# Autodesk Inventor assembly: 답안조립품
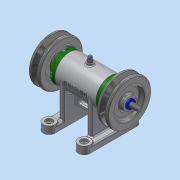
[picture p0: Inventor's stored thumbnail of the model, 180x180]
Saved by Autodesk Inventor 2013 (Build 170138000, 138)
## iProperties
Created: 2015-11
Part Number: 답안조립품
Document SubType Name: Assembly
Designer: ST1
Author: ST1
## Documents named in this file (11)
- C:\Users\ST1\Desktop\451109V1027\답안조립품.iam
- C:\Users\ST1\Desktop\451109V1027\1-본체.ipt
- C:\Users\ST1\Desktop\451109V1027\커버.ipt
- C:\Users\ST1\Desktop\451109V1027\축.ipt
- C:\Users\ST1\Desktop\451109V1027\키 3 x 3 x 12.ipt
- C:\Users\ST1\Desktop\451109V1027\베어링 15 x 32 x 9.ipt
- C:\Users\ST1\Desktop\451109V1027\볼트 M4 x 12.ipt
- C:\Users\ST1\Desktop\451109V1027\V벨트풀리.ipt
- C:\Users\ST1\Desktop\451109V1027\니플 M 6 x 0.75.ipt
- C:\Users\ST1\Desktop\451109V1027\와셔 6x11.5.ipt
- C:\Users\ST1\Desktop\451109V1027\스프링와셔 8.ipt
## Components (13 placed, 4 different names)
1. 1-본체:1
2. KS B 2023 6002 - 15 x 32 x 9:1
3. KS B 2023 6002 - 15 x 32 x 9:2
4. ISO 4762 M4 x 12:2
5. ISO 4762 M4 x 12:3
6. ISO 4762 M4 x 12:4
7. ISO 4762 M4 x 12:5
8. ISO 4762 M4 x 12:6
9. ISO 4762 M4 x 12:7
10. ISO 4762 M4 x 12:8
11. ISO 4762 M4 x 12:9
12. V벨트풀리:1 — 각도:2, 플러쉬:2
13. V벨트풀리:2 — 각도:3, 플러쉬:1
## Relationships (4: Angle 2, Flush 2)
- 각도:2 [Angle]: V벨트풀리:1
- 각도:3 [Angle]: V벨트풀리:2
- 플러쉬:1 [Flush]: V벨트풀리:2
- 플러쉬:2 [Flush]: V벨트풀리:1
